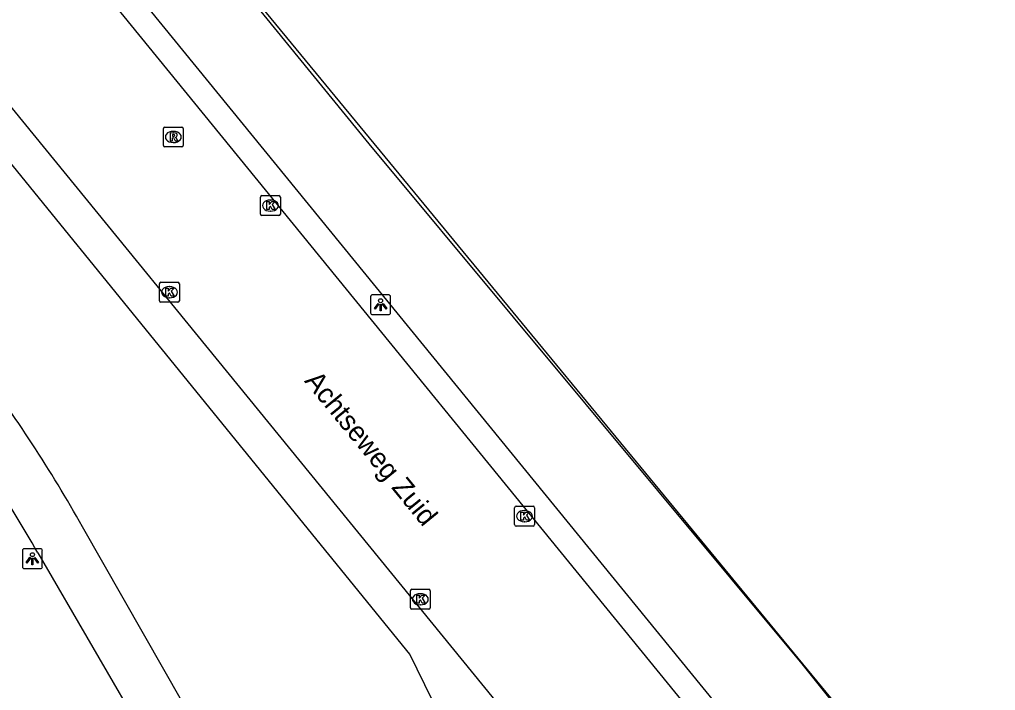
# Model space of a CAD drawing. Extents: x 157154 to 159278, y 385000 to 386650.
# Drawn here: x 159129.42 to 159178.5, y 385385.76 to 385419.5 of the extents above; entities that cross this region are included whole.
import ezdxf

# ---------------------------------------------------------------- set-up
doc = ezdxf.new("R2010")
doc.units = 0
for name, color, linetype in [('IMGEO_Fietspad_gesloten', 7, 'Continuous'), ('IMGEO_Gemengd_bos', 7, 'Continuous'), ('IMGEO_Grasland_overig', 7, 'Continuous'), ('IMGEO_Hek', 7, 'Continuous'), ('IMGEO_Kolk', 7, 'Continuous'), ('IMGEO_Lichtpunt', 7, 'Continuous'), ('IMGEO_Muur', 7, 'Continuous'), ('IMGEO_Openbare_ruimte_label', 7, 'Continuous'), ('IMGEO_Rijbaan_lokaal_open', 7, 'Continuous'), ('IMGEO_Rioolput', 7, 'Continuous'), ('IMGEO_Spoorbaan_halfverhard', 7, 'Continuous')]:
    doc.layers.add(name, color=color, linetype=linetype)

msp = doc.modelspace()

# ---------------------------------------------------------------- linework, layer by layer
at = {"layer": 'IMGEO_Fietspad_gesloten'}
for points in [[(159140.697, 385379.765), (159132.59, 385393.989)], [(159130.342, 385392.676), (159138.639, 385378.397)]]:
    msp.add_lwpolyline(points, dxfattribs=at)
for centre, radius, start, end in [((159070.174, 385358.967), 71.57, 29.29683, 37.11613), ((159064.342, 385355.135), 75.929, 29.63123, 36.69187)]:
    msp.add_arc(centre, radius, start, end, dxfattribs=at)
at = {"layer": 'IMGEO_Gemengd_bos'}
msp.add_lwpolyline([(159150.273, 385385.066), (159150.167, 385385.283), (159149.043, 385387.58), (159057.676, 385500), (159035.861, 385526.812), (159000, 385569.989), (158976.812, 385598.387), (158944.195, 385637.794), (158939.671, 385643.611)], dxfattribs=at)
at = {"layer": 'IMGEO_Grasland_overig'}
msp.add_lwpolyline([(159011.046, 385573.162), (159044.807, 385531.748), (159070.687, 385500), (159100.286, 385463.691), (159167.2, 385381.706)], dxfattribs=at)
at = {"layer": 'IMGEO_Hek'}
msp.add_lwpolyline([(159267.474, 385267.911), (159256.239, 385281.143), (159249.91, 385288.837), (159235.65, 385306.134), (159224.805, 385319.331), (159211.713, 385335.149), (159200.593, 385348.679), (159191.169, 385360.049), (159187.934, 385364.03), (159178.354, 385375.528), (159160.922, 385396.693), (159137.128, 385425.571)], dxfattribs=at)
at = {"layer": 'IMGEO_Kolk'}
for p, q in [((159141.538, 385409.716), (159141.538, 385410.568)), ((159141.613, 385410.642), (159142.465, 385410.642)), ((159142.026, 385410.422), (159142.051, 385410.422)), ((159142.539, 385410.568), (159142.539, 385409.716)), ((159142.049, 385409.862), (159142.024, 385409.862)), ((159142.465, 385409.642), (159141.613, 385409.642)), ((159136.46, 385405.361), (159136.46, 385406.213)), ((159136.535, 385406.287), (159137.387, 385406.287)), ((159136.948, 385406.067), (159136.973, 385406.067)), ((159137.461, 385406.213), (159137.461, 385405.361)), ((159136.971, 385405.507), (159136.946, 385405.507)), ((159137.387, 385405.287), (159136.535, 385405.287)), ((159154.318, 385394.1), (159154.318, 385394.952)), ((159154.393, 385395.026), (159155.245, 385395.026)), ((159154.806, 385394.806), (159154.831, 385394.806)), ((159155.319, 385394.952), (159155.319, 385394.1)), ((159154.829, 385394.246), (159154.804, 385394.246)), ((159155.245, 385394.026), (159154.393, 385394.026)), ((159149.078, 385389.923), (159149.078, 385390.775)), ((159149.153, 385390.849), (159150.005, 385390.849)), ((159150.079, 385390.775), (159150.079, 385389.923)), ((159149.566, 385390.629), (159149.591, 385390.629)), ((159150.005, 385389.849), (159149.153, 385389.849)), ((159149.589, 385390.069), (159149.564, 385390.069))]:
    msp.add_line(p, q, dxfattribs=at)
for points in [[(159141.538, 385409.716), (159141.538, 385410.568)], [(159141.613, 385410.642), (159142.465, 385410.642)], [(159141.859, 385410.342), (159141.982, 385410.342), (159141.982, 385410.191), (159142.112, 385410.342), (159142.276, 385410.342), (159142.13, 385410.191), (159142.283, 385409.942), (159142.131, 385409.942), (159142.046, 385410.106), (159141.982, 385410.039), (159141.982, 385409.942), (159141.859, 385409.942), (159141.859, 385410.342)], [(159142.539, 385410.568), (159142.539, 385409.716)], [(159142.465, 385409.642), (159141.613, 385409.642)], [(159136.46, 385405.361), (159136.46, 385406.213)], [(159136.535, 385406.287), (159137.387, 385406.287)], [(159136.781, 385405.987), (159136.904, 385405.987), (159136.904, 385405.836), (159137.034, 385405.987), (159137.198, 385405.987), (159137.052, 385405.836), (159137.205, 385405.587), (159137.053, 385405.587), (159136.968, 385405.751), (159136.904, 385405.684), (159136.904, 385405.587), (159136.781, 385405.587), (159136.781, 385405.987)], [(159137.461, 385406.213), (159137.461, 385405.361)], [(159137.387, 385405.287), (159136.535, 385405.287)], [(159154.318, 385394.1), (159154.318, 385394.952)], [(159154.393, 385395.026), (159155.245, 385395.026)], [(159154.639, 385394.726), (159154.762, 385394.726), (159154.762, 385394.575), (159154.892, 385394.726), (159155.056, 385394.726), (159154.91, 385394.575), (159155.063, 385394.326), (159154.911, 385394.326), (159154.826, 385394.49), (159154.762, 385394.423), (159154.762, 385394.326), (159154.639, 385394.326), (159154.639, 385394.726)], [(159155.319, 385394.952), (159155.319, 385394.1)], [(159155.245, 385394.026), (159154.393, 385394.026)], [(159149.078, 385389.923), (159149.078, 385390.775)], [(159149.153, 385390.849), (159150.005, 385390.849)], [(159150.079, 385390.775), (159150.079, 385389.923)], [(159149.399, 385390.549), (159149.522, 385390.549), (159149.522, 385390.398), (159149.652, 385390.549), (159149.816, 385390.549), (159149.67, 385390.398), (159149.823, 385390.149), (159149.671, 385390.149), (159149.586, 385390.313), (159149.522, 385390.246), (159149.522, 385390.149), (159149.399, 385390.149), (159149.399, 385390.549)], [(159150.005, 385389.849), (159149.153, 385389.849)]]:
    msp.add_lwpolyline(points, dxfattribs=at)
for centre, start, end in [((159141.615, 385410.566), 91.552, 178.448), ((159141.615, 385410.566), 91.552, 178.448), ((159142.463, 385410.566), 1.552, 88.448), ((159142.463, 385410.566), 1.552, 88.448), ((159141.615, 385409.718), 181.552, 268.448), ((159141.615, 385409.718), 181.552, 268.448), ((159142.463, 385409.718), 271.552, 358.448), ((159142.463, 385409.718), 271.552, 358.448), ((159136.537, 385406.211), 91.552, 178.448), ((159136.537, 385406.211), 91.552, 178.448), ((159137.385, 385406.211), 1.552, 88.448), ((159137.385, 385406.211), 1.552, 88.448), ((159136.537, 385405.363), 181.552, 268.448), ((159136.537, 385405.363), 181.552, 268.448), ((159137.385, 385405.363), 271.552, 358.448), ((159137.385, 385405.363), 271.552, 358.448), ((159154.395, 385394.95), 91.552, 178.448), ((159154.395, 385394.95), 91.552, 178.448), ((159155.243, 385394.95), 1.552, 88.448), ((159155.243, 385394.95), 1.552, 88.448), ((159154.395, 385394.102), 181.552, 268.448), ((159154.395, 385394.102), 181.552, 268.448), ((159155.243, 385394.102), 271.552, 358.448), ((159155.243, 385394.102), 271.552, 358.448), ((159149.155, 385390.773), 91.552, 178.448), ((159149.155, 385390.773), 91.552, 178.448), ((159150.003, 385390.773), 1.552, 88.448), ((159150.003, 385390.773), 1.552, 88.448), ((159149.155, 385389.925), 181.552, 268.448), ((159149.155, 385389.925), 181.552, 268.448), ((159150.003, 385389.925), 271.552, 358.448), ((159150.003, 385389.925), 271.552, 358.448)]:
    msp.add_arc(centre, 0.0765, start, end, dxfattribs=at)
for centre, major_axis, ratio, start_param, end_param in [((159142.025, 385410.142), (-0.387, 0.002), 0.722429, 4.712389, 7.853982), ((159142.05, 385410.142), (-0.39, 0.002), 0.717154, 1.570796, 4.712389), ((159136.947, 385405.787), (-0.387, 0.002), 0.722429, 4.712389, 7.853982), ((159136.972, 385405.787), (-0.39, 0.002), 0.717154, 1.570796, 4.712389), ((159154.805, 385394.526), (-0.387, 0.002), 0.722429, 4.712389, 7.853982), ((159154.83, 385394.526), (-0.39, 0.002), 0.717154, 1.570796, 4.712389), ((159149.565, 385390.349), (-0.387, 0.002), 0.722429, 4.712389, 7.853982), ((159149.59, 385390.349), (-0.39, 0.002), 0.717154, 1.570796, 4.712389)]:
    msp.add_ellipse(centre, major_axis=major_axis, ratio=ratio, start_param=start_param, end_param=end_param, dxfattribs=at)
at = {"layer": 'IMGEO_Lichtpunt'}
for p, q in [((159147.081, 385405.56), (159147.081, 385404.753)), ((159147.081, 385405.56), (159147.081, 385404.753)), ((159147.983, 385405.655), (159147.175, 385405.655)), ((159147.983, 385405.655), (159147.175, 385405.655)), ((159148.077, 385404.753), (159148.077, 385405.56)), ((159148.077, 385404.753), (159148.077, 385405.56)), ((159147.175, 385404.659), (159147.983, 385404.659)), ((159147.175, 385404.659), (159147.983, 385404.659)), ((159129.573, 385392.792), (159129.573, 385391.985)), ((159129.573, 385392.792), (159129.573, 385391.985)), ((159130.475, 385392.887), (159129.667, 385392.887)), ((159130.475, 385392.887), (159129.667, 385392.887)), ((159130.569, 385391.985), (159130.569, 385392.792)), ((159130.569, 385391.985), (159130.569, 385392.792)), ((159129.667, 385391.891), (159130.475, 385391.891)), ((159129.667, 385391.891), (159130.475, 385391.891))]:
    msp.add_line(p, q, dxfattribs=at)
for points in [[(159147.455, 385405.224), (159147.494, 385405.196), (159147.306, 385404.934), (159147.268, 385404.961), (159147.455, 385405.224)], [(159147.557, 385405.176), (159147.604, 385405.176), (159147.604, 385404.854), (159147.557, 385404.854), (159147.557, 385405.176)], [(159147.667, 385405.196), (159147.705, 385405.223), (159147.892, 385404.961), (159147.853, 385404.933), (159147.667, 385405.196)], [(159129.947, 385392.456), (159129.986, 385392.428), (159129.798, 385392.166), (159129.76, 385392.193), (159129.947, 385392.456)], [(159130.049, 385392.408), (159130.096, 385392.408), (159130.096, 385392.086), (159130.049, 385392.086), (159130.049, 385392.408)], [(159130.159, 385392.428), (159130.197, 385392.455), (159130.384, 385392.193), (159130.345, 385392.165), (159130.159, 385392.428)]]:
    msp.add_lwpolyline(points, dxfattribs=at)
for centre in [(159147.58, 385405.358), (159130.072, 385392.59)]:
    msp.add_circle(centre, 0.0994, dxfattribs=at)
for centre, start, end in [((159147.175, 385405.56), 90, 180), ((159147.175, 385405.56), 90, 180), ((159147.983, 385405.56), 0, 90), ((159147.983, 385405.56), 0, 90), ((159147.175, 385404.753), 180, 270), ((159147.175, 385404.753), 180, 270), ((159147.983, 385404.753), 270, 0), ((159147.983, 385404.753), 270, 360), ((159129.667, 385392.792), 90, 180), ((159129.667, 385392.792), 90, 180), ((159130.475, 385392.792), 0, 90), ((159130.475, 385392.792), 0, 90), ((159129.667, 385391.985), 180, 270), ((159129.667, 385391.985), 180, 270), ((159130.475, 385391.985), 270, 0), ((159130.475, 385391.985), 270, 360)]:
    msp.add_arc(centre, 0.0946, start, end, dxfattribs=at)
at = {"layer": 'IMGEO_Muur'}
msp.add_lwpolyline([(159010.937, 385573.296), (159044.807, 385531.748), (159100.286, 385463.691), (159167.2, 385381.706), (159168.34, 385381.585), (159168.595, 385381.558), (159169.474, 385380.494), (159169.729, 385380.185), (159170.502, 385379.248), (159170.444, 385378.688), (159170.356, 385377.836), (159224.612, 385309.725), (159249.549, 385278.463)], dxfattribs=at)
at = {"layer": 'IMGEO_Rijbaan_lokaal_open'}
for points in [[(158854.381, 385763.213), (159043.862, 385530.978), (159167.844, 385378.971)], [(159153.706, 385384.827), (159038.204, 385526.376), (158938.905, 385648.068)]]:
    msp.add_lwpolyline(points, dxfattribs=at)
at = {"layer": 'IMGEO_Rioolput'}
for p, q in [((159136.656, 385413.166), (159136.656, 385414.018)), ((159136.731, 385414.092), (159137.583, 385414.092)), ((159137.144, 385413.872), (159137.169, 385413.872)), ((159137.657, 385414.018), (159137.657, 385413.166)), ((159137.167, 385413.312), (159137.142, 385413.312)), ((159137.583, 385413.092), (159136.731, 385413.092))]:
    msp.add_line(p, q, dxfattribs=at)
for points in [[(159136.656, 385413.166), (159136.656, 385414.018)], [(159136.731, 385414.092), (159137.583, 385414.092)], [(159137.245, 385413.79), (159136.993, 385413.792), (159136.993, 385413.392)], [(159137.657, 385414.018), (159137.657, 385413.166)], [(159136.993, 385413.392), (159137.117, 385413.392), (159137.117, 385413.554), (159137.128, 385413.554)], [(159137.171, 385413.711), (159137.117, 385413.711), (159137.117, 385413.63)], [(159137.117, 385413.63), (159137.169, 385413.63)], [(159137.175, 385413.525), (159137.246, 385413.392), (159137.386, 385413.392), (159137.321, 385413.518)], [(159137.583, 385413.092), (159136.731, 385413.092)]]:
    msp.add_lwpolyline(points, dxfattribs=at)
for centre, radius, start, end in [((159136.733, 385414.016), 0.0765, 91.552, 178.448), ((159136.733, 385414.016), 0.0765, 91.552, 178.448), ((159137.244, 385413.68), 0.109, 350.3612, 89.416), ((159137.581, 385414.016), 0.0765, 1.552, 88.448), ((159137.581, 385414.016), 0.0765, 1.552, 88.448), ((159137.127, 385413.501), 0.0533, 26.0293, 88.6989), ((159137.153, 385413.819), 0.19, 274.7715, 282.9687), ((159137.177, 385413.615), 0.0964, 77.0061, 93.1865), ((159137.191, 385413.672), 0.0378, 276.6634, 79.6772), ((159137.242, 385413.68), 0.112, 277.5842, 350.9817), ((159137.226, 385413.465), 0.108, 29.5134, 73.7905), ((159136.733, 385413.168), 0.0765, 181.552, 268.448), ((159136.733, 385413.168), 0.0765, 181.552, 268.448), ((159137.581, 385413.168), 0.0765, 271.552, 358.448), ((159137.581, 385413.168), 0.0765, 271.552, 358.448)]:
    msp.add_arc(centre, radius, start, end, dxfattribs=at)
for centre, major_axis, ratio, start_param, end_param in [((159137.143, 385413.592), (-0.387, 0.002), 0.722429, 4.712389, 7.853982), ((159137.168, 385413.592), (-0.39, 0.002), 0.717154, 1.570796, 4.712389)]:
    msp.add_ellipse(centre, major_axis=major_axis, ratio=ratio, start_param=start_param, end_param=end_param, dxfattribs=at)
at = {"layer": 'IMGEO_Spoorbaan_halfverhard'}
msp.add_lwpolyline([(159049.516, 385533.221), (159060.741, 385519), (159082.021, 385492.494), (159102.075, 385468.133), (159114.976, 385452.124), (159124.294, 385441.044), (159146.986, 385413.255), (159168.76, 385387.107), (159181.227, 385371.527), (159195.791, 385354.347), (159205.058, 385342.95), (159218.546, 385326.665), (159240.349, 385300.123), (159250.822, 385287.524), (159259.439, 385277.319), (159267.341, 385268.238), (159271.367, 385263.363)], dxfattribs=at)

# ---------------------------------------------------------------- texts
at = {"layer": 'IMGEO_Openbare_ruimte_label'}
msp.add_text('Achtseweg Zuid', height=1, rotation=309.2773, dxfattribs=at).set_placement((159143.717, 385401.311))

doc.saveas('drawing.dxf')
